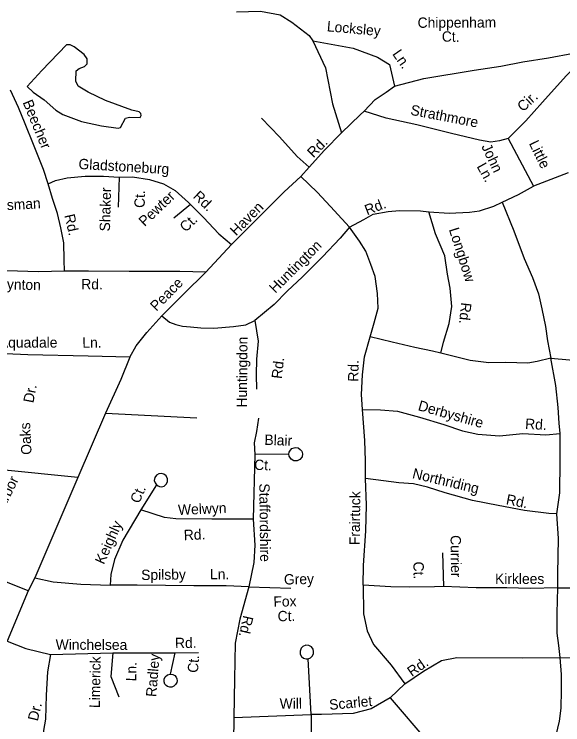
# Model space of a CAD drawing. Extents: x 1551653 to 1702041, y 811336 to 920032.
# Drawn here: x 1606474 to 1609950, y 857198 to 861702 of the extents above; entities that cross this region are included whole.
import ezdxf

# ---------------------------------------------------------------- set-up
doc = ezdxf.new("R2010")
doc.units = 0
for name, color, linetype in [('Old_Level_10', 7, 'Continuous'), ('Old_Level_35', 7, 'Continuous'), ('Old_Level_62', 7, 'Continuous')]:
    doc.layers.add(name, color=color, linetype=linetype)

msp = doc.modelspace()

# ---------------------------------------------------------------- linework, layer by layer
at = {"layer": 'Old_Level_35'}
for p, q in [((1609604.054, 860914.934), (1609765.058, 860611.434)), ((1608342.689, 860731.974), (1608291.296, 860673.524)), ((1609984.696, 860696.984), (1609765.058, 860611.434)), ((1607138.912, 860670.284), (1607133.42, 860478.486)), ((1607592.01, 860495.84), (1607485.205, 860408.741)), ((1607688.996, 860068.192), (1607851.161, 860242.942)), ((1607053.033, 859172.678), (1606877.751, 858765.346)), ((1607053.033, 859172.678), (1607631.341, 859144.877)), ((1607999.04, 858911.5), (1607988.939, 858502.071)), ((1608215.282, 858913.907), (1607999.04, 858911.5)), ((1606877.751, 858765.346), (1606605.76, 858129.195)), ((1607374.883, 858719.605), (1607276.787, 858560.2)), ((1609187.052, 858287.273), (1609194.47, 858074.457)), ((1606605.76, 858129.195), (1606563.498, 858048.352)), ((1606563.498, 858048.352), (1606429.653, 857727.38)), ((1607961.16, 858072.424), (1608227.042, 858063.484)), ((1606705.266, 857642.873), (1607099.332, 857654.397)), ((1607099.332, 857654.397), (1607492.185, 857654.509)), ((1607492.185, 857654.509), (1607463.328, 857519.277)), ((1607492.185, 857654.509), (1607641.182, 857657.036)), ((1608354.897, 857263.072), (1608337.219, 857616.899)), ((1609933.799, 857624.079), (1610361.165, 857616.782)), ((1608949.488, 857457.56), (1608856.05, 857369.103)), ((1608856.05, 857369.103), (1609222.227, 856941.982)), ((1607864.977, 857245.381), (1607862.333, 856943.185)), ((1607864.977, 857245.381), (1608354.897, 857263.072)), ((1608354.897, 857263.072), (1608359.829, 856627.268))]:
    msp.add_line(p, q, dxfattribs=at)
for points in [[(1607882.397, 861718.054), (1608034.598, 861722.353), (1608158.644, 861698.866), (1608232.401, 861651.893), (1608343.036, 861568.013), (1608366.504, 861534.461)], [(1608366.504, 861534.461), (1608621.301, 861487.488), (1608775.52, 861430.45), (1608852.629, 861383.476), (1608882.802, 861245.913)], [(1608366.504, 861534.461), (1608446.967, 861363.345), (1608490.55, 861135.191), (1608547.544, 860950.654)], [(1608882.802, 861245.913), (1609070.155, 861294.101), (1609389.179, 861346.664), (1609556.472, 861373.92), (1609697.082, 861400.829), (1609860.484, 861426.137), (1610018.051, 861455.339), (1610103.111, 861478.192)], [(1609604.054, 860914.934), (1609716.88, 861025.901), (1609820.964, 861144.558), (1609972.033, 861311.588), (1610026.981, 861366.706), (1610103.111, 861478.192)], [(1608692.365, 861088.421), (1608760.858, 861161.719), (1608830.887, 861208.442), (1608882.802, 861245.913)], [(1606688.582, 860626.389), (1606660.239, 860718.817), (1606597.191, 860875.982), (1606543.818, 861006.94), (1606501.719, 861111.651), (1606451.699, 861220.525)], [(1608547.544, 860950.654), (1608665.54, 861064.38), (1608692.365, 861088.421)], [(1609604.054, 860914.934), (1609549.587, 860899.36), (1609493.174, 860891.573), (1609423.144, 860903.253), (1609244.179, 860946.083), (1609026.309, 861000.593), (1608829.967, 861043.405), (1608692.365, 861088.421)], [(1608342.689, 860731.974), (1608266.134, 860799.496), (1608154.629, 860925.428), (1608040.964, 861043.6)], [(1608547.544, 860950.654), (1608441.178, 860840.649), (1608342.689, 860731.974)], [(1606688.582, 860626.389), (1606736.836, 860647.623), (1606809.251, 860666.166), (1606923.312, 860676.058), (1607039.175, 860676.107), (1607138.912, 860670.284)], [(1607138.912, 860670.284), (1607222.764, 860670.582), (1607332.501, 860654.749), (1607419.788, 860627.164), (1607494.991, 860585.815), (1607578.371, 860508.22), (1607592.01, 860495.84)], [(1608291.296, 860673.524), (1608183.808, 860577.278), (1607978.283, 860369.332), (1607851.161, 860242.942)], [(1608597.908, 860351.825), (1608550.926, 860406.266), (1608478.645, 860483.83), (1608394.458, 860575.391), (1608291.296, 860673.524)], [(1606792.21, 860072.778), (1606791.672, 860144.832), (1606787.656, 860252.771), (1606769.402, 860349.195), (1606749.021, 860439.461), (1606716.922, 860533.965), (1606688.582, 860626.389)], [(1609566.321, 860510.09), (1609670.174, 860559.582), (1609765.058, 860611.434)], [(1607592.01, 860495.84), (1607673.613, 860414.497), (1607771.562, 860310.852), (1607851.161, 860242.942)], [(1609101.459, 860450.699), (1609229.431, 860440.557), (1609358.617, 860448.225), (1609421.703, 860456.287), (1609514.163, 860486.428), (1609566.321, 860510.09)], [(1609566.321, 860510.09), (1609640.502, 860329.444), (1609704.791, 860153.746), (1609757.732, 860033.964), (1609795.829, 859929.335), (1609816.408, 859835.229), (1609840.145, 859722.883), (1609852.379, 859632.869), (1609874.633, 859522.172)], [(1608597.908, 860351.825), (1608688.469, 860400.735), (1608749.007, 860435.528), (1608843.273, 860451.088), (1608915.241, 860457.63), (1609047.934, 860455.758), (1609101.459, 860450.699)], [(1609177.339, 859553.682), (1609194.648, 859622.97), (1609229.266, 859741.752), (1609246.574, 859850.635), (1609236.84, 859966.761), (1609220.426, 860055.143), (1609202.839, 860171.069), (1609143.495, 860309.646), (1609101.459, 860450.699)], [(1608597.908, 860351.825), (1608539.731, 860283.101), (1608427.681, 860165.106), (1608301.187, 860037.55), (1608204.255, 859947.516), (1608120.917, 859861.587), (1607999.7, 859760.493)], [(1608729.786, 859657.615), (1608754.765, 859746.452), (1608780.885, 859839.582), (1608775.94, 859931.142), (1608760.629, 860040.359), (1608734.162, 860116.74), (1608701.759, 860200.874), (1608662.197, 860262.739), (1608597.908, 860351.825)], [(1607207.459, 859528.285), (1606942.51, 859534.451), (1606560.492, 859543.701), (1606418.776, 859549.867), (1606314.029, 859537.534), (1606193.878, 859574.533), (1606116.858, 859688.612), (1606082.969, 859805.773), (1606067.565, 859947.601), (1606105.095, 860075.314)], [(1606792.21, 860072.778), (1606628.264, 860069.901), (1606426.673, 860075.593), (1606224.918, 860073.284), (1606105.095, 860075.314)], [(1607688.996, 860068.192), (1607523.577, 860071.548), (1607399.515, 860071.863), (1607201.802, 860071.473), (1606944.119, 860074.101), (1606792.21, 860072.778)], [(1607409.998, 859789.492), (1607548.541, 859930.961), (1607688.996, 860068.192)], [(1607207.459, 859528.285), (1607246.681, 859600.699), (1607314.233, 859685.378), (1607409.998, 859789.492)], [(1607409.998, 859789.492), (1607457.632, 859750.505), (1607497.572, 859735.22), (1607540.503, 859725.111), (1607591.01, 859720.056), (1607657.36, 859714.377), (1607738.589, 859711.385), (1607862.694, 859723.074), (1607940.951, 859733.694), (1607999.7, 859760.493)], [(1607999.7, 859760.493), (1608019.903, 859629.072), (1608009.801, 859515.342), (1608007.319, 859415.769), (1608009.845, 859324.784)], [(1608680.332, 859197.338), (1608675.387, 859291.373), (1608681.604, 859416.823), (1608693.713, 859530.442), (1608729.786, 859657.615)], [(1609177.339, 859553.682), (1609123.98, 859566.433), (1609011.67, 859590.801), (1608869.594, 859622.602), (1608729.786, 859657.615)], [(1607207.459, 859528.285), (1607148.997, 859387.501), (1607053.033, 859172.678)], [(1609874.633, 859522.172), (1609788.089, 859501.715), (1609728.385, 859490.913), (1609588.197, 859495.45), (1609482.298, 859493.396), (1609362.79, 859506.664), (1609177.339, 859553.682)], [(1609933.977, 859043.912), (1609926.559, 859110.727), (1609920.265, 859209.237), (1609906.899, 859349.387), (1609874.633, 859522.172)], [(1609874.633, 859522.172), (1609992.555, 859512.166), (1610091.928, 859488.337), (1610165.084, 859457.447), (1610202.175, 859422.802), (1610233.091, 859376.82), (1610291.601, 859301.791)], [(1606877.751, 858765.346), (1606394.067, 858814.677), (1606400.228, 859348.072)], [(1608699.935, 858758.412), (1608699.935, 858872.244), (1608695.168, 858999.37), (1608680.332, 859197.338)], [(1608680.332, 859197.338), (1608796.064, 859194.534), (1608903.76, 859186.548), (1609043.05, 859147.376), (1609196.025, 859102.648), (1609314.84, 859060.658), (1609412.29, 859040.871), (1609549.951, 859030.474), (1609697.556, 859045.298), (1609843.261, 859036.739), (1609933.977, 859043.912)], [(1608021.769, 859141.488), (1608009.142, 859058.086), (1607993.989, 858984.793), (1607999.04, 858911.5)], [(1609911.544, 858535.697), (1609931.326, 858669.326), (1609933.799, 858869.769), (1609933.977, 859043.912)], [(1608215.282, 858913.907), (1608216.933, 858926.282), (1608223.986, 858938.546), (1608234.193, 858948.543), (1608247.71, 858953.874), (1608259.347, 858955.439), (1608273.504, 858952.949), (1608287.123, 858943.667), (1608295.709, 858932.886), (1608300.764, 858915.777), (1608297.772, 858896.427), (1608284.816, 858879.278), (1608266.831, 858870.639), (1608246.827, 858871.043), (1608228.028, 858881.43), (1608216.601, 858900.075), (1608215.282, 858913.907)], [(1607395.473, 858708.582), (1607408.652, 858707.315), (1607424.351, 858711.8), (1607437.383, 858722.742), (1607445.516, 858738.985), (1607446.471, 858756.577), (1607437.281, 858776.974), (1607422.094, 858787.886), (1607404.364, 858791.849), (1607389.903, 858789.139), (1607375.509, 858780.028), (1607365.011, 858765.632), (1607362.019, 858746.282), (1607366.313, 858731.187), (1607374.883, 858719.605), (1607385.336, 858711.99), (1607395.473, 858708.582)], [(1608685.55, 858083.678), (1608688.022, 858207.408), (1608702.877, 858428.196), (1608705.761, 858590.03), (1608699.935, 858758.412)], [(1609911.544, 858535.697), (1609862.509, 858536.86), (1609707.011, 858555.823), (1609539.793, 858588.831), (1609378.53, 858619.72), (1609205.634, 858668.854), (1609092.307, 858704.973), (1609004.899, 858726.557), (1608911.163, 858732.259), (1608813.351, 858744.051), (1608699.935, 858758.412)], [(1607276.787, 858560.2), (1607163.145, 858368.122), (1607110.113, 858246.81), (1607087.385, 858150.771), (1607082.334, 858082.533)], [(1607988.939, 858502.071), (1607726.301, 858502.071), (1607499.019, 858504.598), (1607425.783, 858512.18), (1607276.787, 858560.2)], [(1609917.827, 858067.034), (1609919.137, 858155.094), (1609923.278, 858378.932), (1609911.544, 858535.697)], [(1607988.939, 858502.071), (1607999.04, 858337.794), (1607991.465, 858226.591), (1607961.16, 858072.424)], [(1606563.498, 858048.352), (1606410.429, 858109.196), (1606165.469, 858192.598), (1605981.118, 858230.508), (1605905.357, 858230.508)], [(1606605.76, 858129.195), (1606721.926, 858103.922), (1606896.176, 858088.758), (1607082.334, 858082.533)], [(1607961.16, 858072.424), (1607817.215, 858080.006), (1607612.66, 858080.006), (1607254.059, 858082.533), (1607082.334, 858082.533)], [(1609194.47, 858074.457), (1609136.974, 858073.622), (1608979.025, 858070.423), (1608861.109, 858073.779), (1608685.55, 858083.678)], [(1608685.55, 858083.678), (1608686.85, 857902.371), (1608709.578, 857793.695), (1608749.984, 857707.766), (1608863.626, 857576.344), (1608949.488, 857457.56)], [(1607961.16, 858072.424), (1607902.858, 857867.105), (1607875.079, 857715.465), (1607870.028, 857488.005), (1607864.977, 857245.381)], [(1609917.827, 858067.034), (1609742.267, 858062.084), (1609596.488, 858067.205), (1609400.776, 858066.775), (1609194.47, 858074.457)], [(1609933.799, 857624.079), (1609923.908, 857700.792), (1609914.017, 857779.979), (1609915.355, 857906.184), (1609917.827, 858067.034)], [(1609917.827, 858067.034), (1610066.188, 858067.034), (1610184.876, 858062.084), (1610271.42, 858059.61), (1610387.635, 858062.084)], [(1606429.653, 857727.38), (1606548.803, 857682.197), (1606705.266, 857642.873)], [(1608337.219, 857616.899), (1608351.934, 857622.204), (1608362.751, 857632.591), (1608370.251, 857647.247), (1608371.383, 857663.635), (1608367.869, 857677.713), (1608356.95, 857691.942), (1608341.717, 857700.656), (1608321.337, 857702.07), (1608303.381, 857694.832), (1608292.334, 857683.047), (1608285.172, 857665.383), (1608286.583, 857646.144), (1608294.099, 857631.984), (1608306.881, 857620.918), (1608324.181, 857615.364), (1608337.219, 857616.899)], [(1606705.266, 857642.873), (1606685.064, 857534.198), (1606677.488, 857385.085), (1606672.437, 857233.444), (1606659.81, 857162.679), (1606654.759, 857079.277), (1606636.425, 857032.251)], [(1607099.332, 857654.397), (1607085.602, 857505.396), (1607136.109, 857376.502)], [(1608949.488, 857457.56), (1609068.18, 857538.434), (1609181.821, 857606.672), (1609277.785, 857624.364), (1609691.944, 857621.836), (1609933.799, 857624.079)], [(1609714.288, 856902.352), (1609762.785, 856935.386), (1609827.486, 856968.293), (1609861.981, 857001.61), (1609884.796, 857041.17), (1609908.464, 857132.742), (1609930.088, 857222.154), (1609939.553, 857304.008), (1609941.662, 857417.83), (1609941.492, 857517.888), (1609933.799, 857624.079)], [(1607463.328, 857519.277), (1607479.092, 857517.154), (1607491.149, 857509.707), (1607499.938, 857499.123), (1607504.135, 857489.031), (1607505.706, 857477.594), (1607504.069, 857466.019), (1607497.196, 857452.752), (1607486.585, 857442.561), (1607472.675, 857437.44), (1607461.051, 857436.676), (1607446.323, 857440.576), (1607436.451, 857447.181), (1607428.816, 857455.54), (1607423.711, 857470.252), (1607423.866, 857487.66), (1607431.382, 857503.116), (1607445.427, 857514.838), (1607453.298, 857518.08), (1607463.328, 857519.277)], [(1608856.05, 857369.103), (1608736.038, 857298.641), (1608622.397, 857270.841), (1608420.368, 857263.259), (1608354.897, 857263.072)]]:
    msp.add_lwpolyline(points, dxfattribs=at)
at = {"layer": 'Old_Level_62'}
msp.add_lwpolyline([(1606648.588, 861344.858), (1606556.724, 861244.587), (1606594.556, 861208.805), (1606663.761, 861160.208), (1606738.503, 861094.386), (1606782.076, 861066.192), (1606901.007, 861021.798), (1607026.806, 860994.629), (1607132.613, 860980.993), (1607147.992, 860983.658), (1607180.083, 861043.533), (1607204.996, 861048.967), (1607271.843, 861047.224), (1607279.635, 861059.63), (1607275.944, 861073.984), (1607265.589, 861082.698), (1607219.863, 861094.694), (1607052.438, 861155.8), (1606942.222, 861208.703), (1606880.501, 861246.638), (1606865.635, 861277.395), (1606866.353, 861343.32), (1606886.55, 861358.391), (1606919.154, 861371.412), (1606936.481, 861387.406), (1606936.891, 861419.907), (1606918.129, 861447.794), (1606854.665, 861496.288), (1606828.008, 861508.079), (1606805.042, 861507.361), (1606648.588, 861344.858)], dxfattribs=at)

# ---------------------------------------------------------------- texts
at = {"layer": 'Old_Level_10'}
for s, height, rotation, p in [('Chippenham', 65.6167, 0.277269, (1609030.257, 861615.952)), ('Locksley', 65.6167, 354.845494, (1608453.356, 861594.11)), ('Ct.', 65.6167, 359.102592, (1609183.102, 861528.846)), ('Ln.', 65.6167, 304.746753, (1608867.354, 861450.261)), ('Cir.', 65.6167, 43.064669, (1609698.418, 861080.081)), ('Beecher', 65.6167, 292.173642, (1606526.926, 861143.927)), ('Strathmore', 65.6167, 349.096803, (1608981.396, 861065.396)), ('Rd.', 65.6167, 45.374806, (1608370.118, 860788.557)), ('John', 65.6167, 295.13855, (1609432.836, 860863.744)), ('Little', 65.6167, 296.014411, (1609733.953, 860883.496)), ('Gladstoneburg', 65.61666, 356.6584, (1606880.116, 860721.852)), ('Ln.', 65.6167, 298.8229, (1609402.538, 860737.924)), ('Shaker', 65.6167, 88.359786, (1607080.569, 860324.815)), ('Ct.', 65.6167, 88.359786, (1607300.685, 860473.787)), ('Pewter', 65.6167, 43.719892, (1607300.773, 860352.888)), ('Rd.', 65.6167, 315.837578, (1607603.126, 860542.977)), ('Grossman', 65.6167, 3.268817, (1606239.284, 860449.431)), ('Rd.', 65.6167, 21.08655, (1608709.812, 860427.184)), ('Haven', 65.6167, 45.335517, (1607880.777, 860293.511)), ('Rd.', 65.6167, 282.723142, (1606791.783, 860427.772)), ('Ct.', 65.6167, 43.719892, (1607560.558, 860317.036)), ('Longbow', 65.6167, 287.674681, (1609227.499, 860338.13)), ('Huntington', 65.6167, 45.088272, (1608128.739, 859930.256)), ('Wessynton', 65.6167, 358.382589, (1606208.228, 859965.026)), ('Rd.', 65.6167, 359.415697, (1606898.877, 859959.056)), ('Peace', 65.6167, 45.598794, (1607375.264, 859815.819)), ('Rd.', 65.6167, 263.780714, (1609306.968, 859877.28)), ('Aquadale', 65.6167, 0.029439, (1606377.483, 859589.033)), ('Ln.', 65.6167, 0.112075, (1606906.145, 859588.266)), ('Huntingdon', 65.6167, 89.490131, (1607948.661, 859209.085)), ('Rd.', 65.6167, 83.036344, (1608169.176, 859388.623)), ('Rd.', 65.6167, 89.022506, (1608654.671, 859372.573)), ('Dr.', 65.6167, 78.979958, (1606595.373, 859234.757)), ('Derbyshire', 65.6167, 344.227603, (1609028.229, 859193.32)), ('Rd.', 65.6167, 356.637925, (1609710.001, 859074.665)), ('Oaks', 65.6167, 92.886647, (1606584.942, 858911.27)), ('Blair', 65.6167, 357.934428, (1608058.755, 858973.056)), ('Ct.', 65.6167, 357.934428, (1607993.665, 858814.41)), ('Northriding', 65.61666, 346.542278, (1608992.672, 858762.386)), ('Arbor', 65.6167, 64.364753, (1606411.552, 858560.761)), ('Staffordshire', 65.61666, 270.702531, (1608026.87, 858727.899)), ('Ct.', 65.6167, 66.322411, (1607265.689, 858596.141)), ('Frairtuck', 65.6167, 89.336392, (1608663.447, 858336.467)), ('Rd.', 65.6167, 348.833469, (1609586.919, 858596.762)), ('Welwyn', 65.6167, 2.344508, (1607513.439, 858528.063)), ('Keighly', 65.6167, 65.799417, (1607042.62, 858210.253)), ('Rd.', 65.6167, 2.344508, (1607549.853, 858368.008)), ('Currier', 65.6167, 270.744994, (1609238.553, 858400.054)), ('Ct.', 65.6167, 270.744994, (1609003.381, 858232.601)), ('Spilsby', 65.6167, 0.768872, (1607279.243, 858115.531)), ('Ln.', 65.6167, 0.240578, (1607714.996, 858120.358)), ('Grey', 65.6167, 1.231608, (1608183.855, 858086.938)), ('Kirklees', 65.6167, 359.934592, (1609520.745, 858091.372)), ('Fox', 65.6167, 1.231608, (1608117.094, 857946.187)), ('Ct.', 65.6167, 1.231608, (1608143.952, 857853.868)), ('Rd.', 65.6167, 257.019731, (1607926.815, 857895.014)), ('Winchelsea', 65.6167, 359.8387, (1606736.943, 857673.916)), ('Rd.', 65.6167, 1.119919, (1607493.532, 857683.868)), ('Limerick', 65.6167, 88.983292, (1607016.671, 857304.208)), ('Radley', 65.6167, 85.295447, (1607373.786, 857372.835)), ('Ct.', 65.6167, 85.295447, (1607637.638, 857525.718)), ('Ln.', 65.6167, 88.983292, (1607247.184, 857473.476)), ('Rd.', 65.6167, 35.189675, (1608993.82, 857500.118)), ('Will', 65.6167, 0.566844, (1608156.531, 857299.768)), ('Scarlet', 65.6167, 5.294011, (1608473.093, 857292.356)), ('Dr.', 65.6167, 76.269314, (1606622.957, 857218.013))]:
    msp.add_text(s, height=height, rotation=rotation, dxfattribs=at).set_placement(p)

doc.saveas('drawing.dxf')
